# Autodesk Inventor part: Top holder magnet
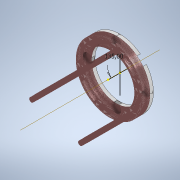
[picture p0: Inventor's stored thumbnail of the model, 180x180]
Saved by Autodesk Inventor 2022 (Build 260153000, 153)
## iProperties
Created: 2023-01
Part Number: Top holder magnet
Material: Generic
Document SubType Name: Modeling
Designer: tmass
Density: 1 g/cm^3
Appearance: Default
Author: tmass
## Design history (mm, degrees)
node "holder"
  node "MeshFeature1"
sketch "Sketch1"
  geometry: L1 (15.168, 16.618)-(15.168, -92.589); L2 (67.606, -31.157)-(-2.46, -31.157); C1 r 5.5 at (15.172, 2.351); C2 r 39.008 at (15.168, -31.157) reference; C3 r 5.5 at (-18.34, -31.153); C4 r 5.5 at (15.165, -64.665); C5 r 5.5 at (48.676, -31.16); C6 r 28.999 at (15.172, -31.15) reference; C7 r 39.015 at (15.172, -31.15); C8 r 28.999 at (15.172, -31.15); 9 further points
  constraints: 6 centre point, 4 end point, 2 coincident, 1 concentric, 1 horizontal, 1 tangent, 1 vertical, 9 other
  dimensions: "d0" = 11 diameter of C1; "d3" = 360 deg dimension on C2.centre C1.centre (derived)
extrude "Extrusion1" new body sketch "Sketch1" distance "d5" = 4; taper "d6" = 0 deg
extrude "Extrusion2" cut sketch "Sketch1" distance "d7" = 3.5; taper "d8" = 0 deg
sketch "Sketch3"
  geometry: 1 further point
sketch "Sketch4"
  geometry: L1 (15.172, -11.963)-(15.172, -53.903); L2 (30.397, -46.375)-(6.499, -22.477); 1 further point
  constraints: 4 end point, 2 point on line, 1 vertical
  dimensions: "d9" = 135 deg angle of L1 L2
workplane "Work Plane1"
sketch "Sketch5"
  geometry: L1 (50.532, 0)-(50.532, 4) reference; L2 (50.532, -1.928)-(46.568, 5.213); L3 (46.568, 5.213)-(63.398, 5.213); L4 (63.398, 5.213)-(68.729, -4.392); L5 (68.729, -4.392)-(51.899, -4.392); L6 (51.899, -4.392)-(50.532, -1.928); 1 further point
  constraints: 10 end point, 2 parallel, 2 point on line, 1 collinear, 1 perpendicular
extrude "Extrusion3" cut sketch "Sketch5" stored distance "d11" = 10; taper "d12" = 0 deg
body "Solid1"
other parameters: "d10" = 90 deg
